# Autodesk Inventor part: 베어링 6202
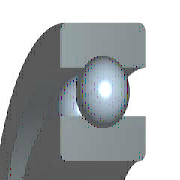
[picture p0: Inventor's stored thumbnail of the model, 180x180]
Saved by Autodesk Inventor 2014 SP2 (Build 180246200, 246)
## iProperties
IsCustomPart: 1
Created: 2015-12
Part Number: 베어링 6202
Material: 강철, 연강
Description: 깊은 그루브 볼 베어링
Document SubType Name: Modeling
Standard: KS B 2023
Designer: mdu
Standards Organization: KS
Language: ko-KR
Size Designation: 6202 - 15 x 35 x 11
Categories: <MemberInstance><Categories><Category DisplayName="샤프트 부품" InternalName="7f7aeb1f-a693-4053-b835-cee3144e0d98" Mnemonic="SHFT"><Category DisplayName="베어링" Inter
Density: 7.86 g/cm^3
Mass: 45.8724 g
Surface Area: 51.5584 cm^2
Volume: 5.83618 cm^3
Appearance: 노란색
Author: mdu
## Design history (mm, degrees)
sketch "스케치" dims "d0" = 5.2 (= -0.26 x WD + 0.26 x BD)
  geometry: L1 (2.9, 12.5)-(8.1, 12.5); L2 (5.5, 12.5)-(5.5, 9.9); L3 (5.5, 12.5)-(5.5, 15.1); L4 (3.568, 10.76)-(0, 10.76); L5 (0, 7.5)-(11, 7.5); L6 (3.568, 14.24)-(0, 14.24); L7 (0, 17.5)-(11, 17.5); L8 (11, 7.5)-(11, 10.76); L9 (7.432, 10.76)-(11, 10.76); L10 (7.432, 14.24)-(11, 14.24); L11 (11, 17.5)-(11, 14.24); L12 (-1.4, 0)-(8.4, 0) reference; L13 (0, -0.3)-(0, 5.3) reference
  constraints: 22 end point, 4 point on line, 2 collinear, 2 perpendicular, 2 symmetric about line, 1 midpoint, 1 parallel, 14 other
  dimensions: "d9" = 15 diameter of L5 L12 (= WD); "d11" = 35 diameter of L7 L12 (= BD); "d12" = 11 distance between parallel lines of L8 L13 (= KB); "d13" = 21.52 diameter of L9 L12 (= 0.326 x BD + 0.674 x WD)
revolve "본체" stored, may be unused: angle "d6" = 90 deg
revolve "볼" stored, may be unused: angle "d7" = 90 deg
pattern_circular "IDS_ARRAYBALL[SIMPL:T]" dims angle "d3" = 360 deg
body "Solid1"
fillet "모깎기1" dims "d1" = 0.6 (= KRS)
other parameters: "WD" = 15 [user parameter; used in 5 equation terms], "BD" = 35 [user parameter; used in 5 equation terms], "KB" = 11 [user parameter; used in 1 equation term], "KRS" = 0.6 [user parameter; used in 1 equation term], "d4" = 0, "d5" = 0, "d8" = 0, "d14" = 0, "d15" = 0, "BBA" = 0 [user parameter], "BC0" = 3750000 [user parameter], "BC" = 7800000 [user parameter], "BR" = 17.5 (= 0.5 x BD) [user parameter], "WR" = 7.5 (= 0.5 x WD) [user parameter]
